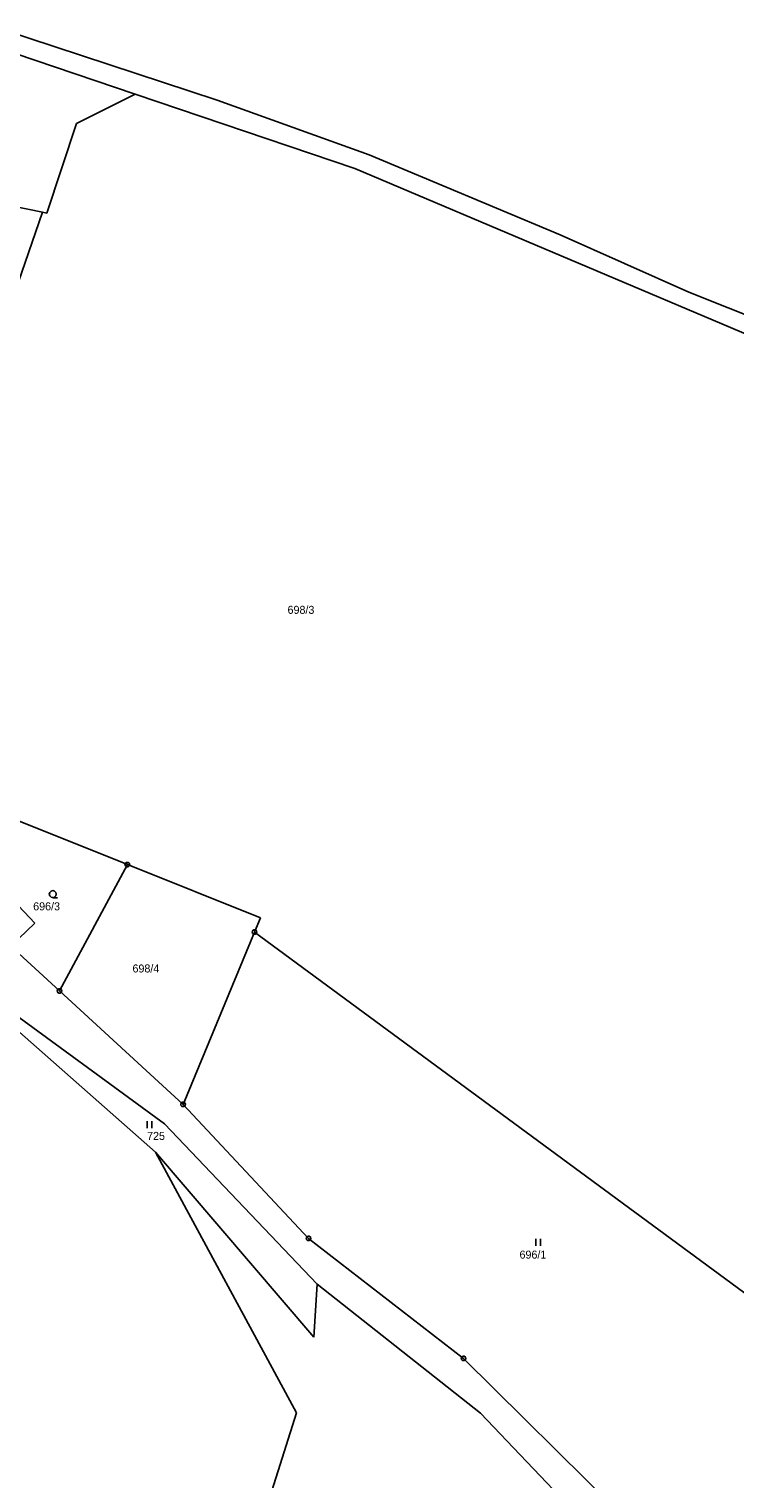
# Model space of a CAD drawing. Extents: x -852001 to -848657, y -1054973 to -1052182.
# Drawn here: x -850483.1 to -850333.2, y -1053768.6 to -1053460.7 of the extents above; entities that cross this region are included whole.
import ezdxf

# ---------------------------------------------------------------- set-up
doc = ezdxf.new("R2010")
doc.units = 0
for name, color, linetype in [('KN_HRANICE', 7, 'Continuous'), ('KN_KULTURY', 7, 'Continuous'), ('KN_MEZNIKY', 7, 'Continuous'), ('KN_PARCELY', 7, 'Continuous')]:
    doc.layers.add(name, color=color, linetype=linetype)

# ---------------------------------------------------------------- blocks, each defined once
blk = doc.blocks.new('304')
blk.add_lwpolyline([(0, 0), (-0.38, 0.1), (-0.65, 0.37), (-0.75, 0.74), (-0.65, 1.11), (-0.38, 1.38), (-0.01, 1.48), (0.36, 1.38), (0.63, 1.11), (0.73, 0.73), (0.63, 0.35), (0.36, 0.08), (-0.02, -0.02), (0.98, -0.02)])
blk = doc.blocks.new('306')
for p, q in [((-0.5, 1.5), (-0.5, 0)), ((0.5, 0), (0.5, 1.5))]:
    blk.add_line(p, q)
blk = doc.blocks.new('105')
blk.add_line((-0.12, 0), (0.12, 0))
blk.add_lwpolyline([(0.15, 0.48), (0.4, 0.3), (0.5, 0.01), (0.4, -0.28), (0.15, -0.46), (-0.16, -0.46), (-0.41, -0.28), (-0.51, 0.01), (-0.41, 0.3), (-0.16, 0.48), (0.15, 0.48)])

msp = doc.modelspace()

# ---------------------------------------------------------------- linework, layer by layer
at = {"layer": 'KN_HRANICE'}
for p, q in [((-850489.13, -1053460.73), (-850443.14, -1053475.85)), ((-850486.02, -1053465.93), (-850460.49, -1053474.58)), ((-850461.37, -1053475.02), (-850472.98, -1053480.79)), ((-850460.49, -1053474.58), (-850461.37, -1053475.02)), ((-850460.49, -1053474.58), (-850413.89, -1053490.38)), ((-850443.14, -1053475.85), (-850410.83, -1053487.45)), ((-850472.98, -1053480.79), (-850479.28, -1053499.87)), ((-850410.83, -1053487.45), (-850370.3, -1053504.45)), ((-850317.08, -1053531.39), (-850413.89, -1053490.38)), ((-850480.2, -1053499.68), (-850493.13, -1053497)), ((-850488.23, -1053523.1), (-850480.2, -1053499.68)), ((-850479.28, -1053499.87), (-850480.2, -1053499.68)), ((-850370.3, -1053504.45), (-850343, -1053516.63)), ((-850343, -1053516.63), (-850313.47, -1053528.44)), ((-850501.57, -1053622.5), (-850462.18, -1053638.28)), ((-850462.18, -1053638.28), (-850476.59, -1053665.13)), ((-850462.18, -1053638.28), (-850433.91, -1053649.6)), ((-850486.44, -1053645.86), (-850481.82, -1053650.71)), ((-850486.95, -1053655.61), (-850481.82, -1053650.71)), ((-850433.91, -1053649.6), (-850435.17, -1053652.63)), ((-850435.17, -1053652.63), (-850450.35, -1053689.23)), ((-850435.17, -1053652.63), (-850325.9, -1053733.17)), ((-850456.22, -1053699.36), (-850505.26, -1053656.14)), ((-850505.26, -1053656.14), (-850454.26, -1053693.33)), ((-850476.59, -1053665.13), (-850486.95, -1053655.61)), ((-850450.35, -1053689.23), (-850476.59, -1053665.13)), ((-850423.7, -1053717.72), (-850450.35, -1053689.23)), ((-850454.26, -1053693.33), (-850421.88, -1053727.44)), ((-850426.25, -1053754.8), (-850456.22, -1053699.36)), ((-850456.22, -1053699.36), (-850422.58, -1053738.67)), ((-850390.8, -1053743.21), (-850423.7, -1053717.72)), ((-850421.88, -1053727.44), (-850422.58, -1053738.67)), ((-850387.2, -1053754.86), (-850421.88, -1053727.44)), ((-850345.83, -1053787.76), (-850390.8, -1053743.21)), ((-850431.5, -1053771.32), (-850426.25, -1053754.8)), ((-850347.05, -1053797.05), (-850387.2, -1053754.86))]:
    msp.add_line(p, q, dxfattribs=at)

# ---------------------------------------------------------------- block references
at = {"layer": 'KN_KULTURY'}
for name, p in [('304', (-850478, -1053645.3)), ('306', (-850457.49, -1053694.27)), ('306', (-850375, -1053719.3))]:
    msp.add_blockref(name, p, dxfattribs=at)
at = {"layer": 'KN_MEZNIKY'}
for p in [(-850462.18, -1053638.28), (-850435.17, -1053652.63), (-850476.59, -1053665.13), (-850450.35, -1053689.23), (-850423.7, -1053717.72), (-850390.8, -1053743.21)]:
    msp.add_blockref('105', p, dxfattribs=at)

# ---------------------------------------------------------------- texts
at = {"layer": 'KN_PARCELY'}
for s, p in [('698/3', (-850428.17, -1053585)), ('696/3', (-850482.17, -1053648)), ('698/4', (-850461.09, -1053661.2)), ('725', (-850457.99, -1053696.78)), ('696/1', (-850378.93, -1053722))]:
    msp.add_text(s, height=1.7, dxfattribs=at).set_placement(p)

doc.saveas('drawing.dxf')
